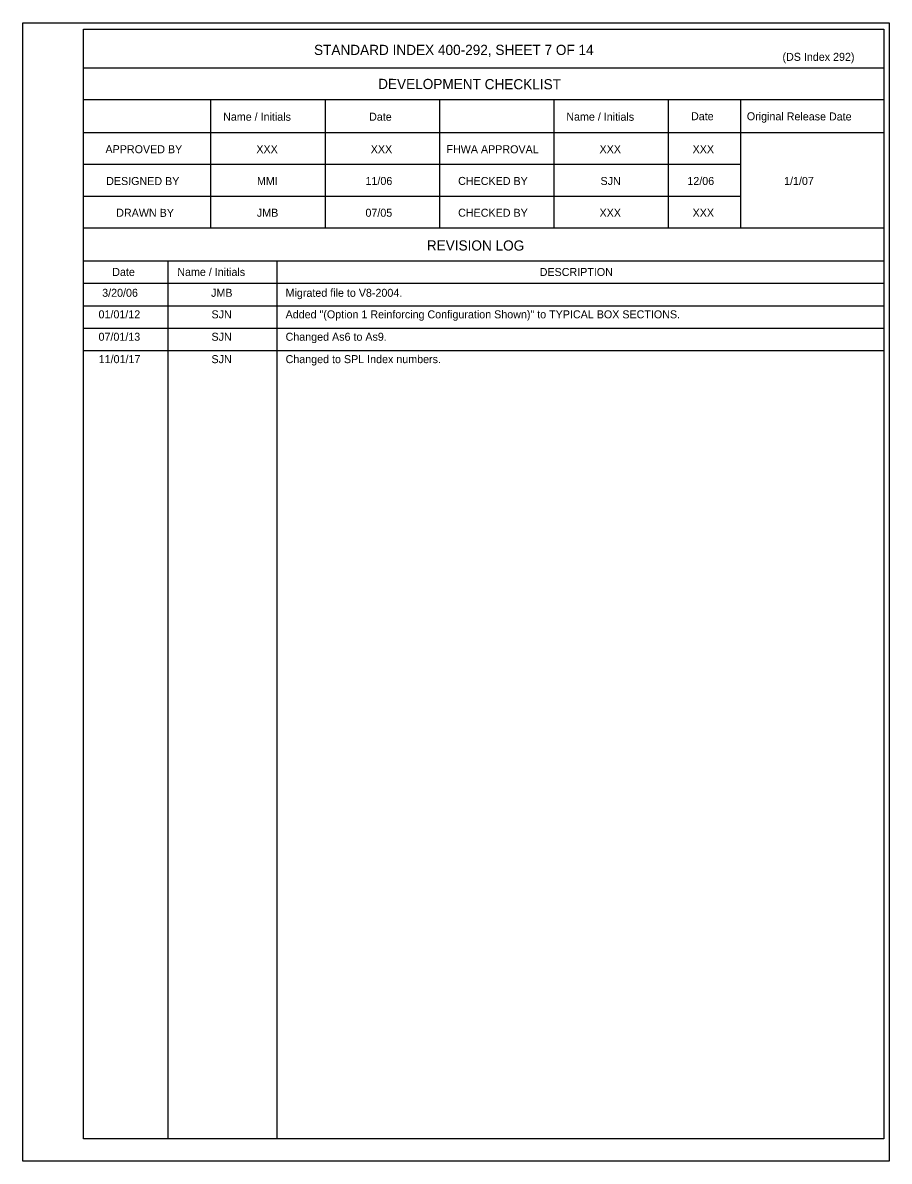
# Model space of a CAD drawing. Extents: x 10340.6 to 10393.7, y 76372.2 to 76398.3.
# Drawn here: x 10377.31 to 10393.67, y 76375.45 to 76396.95 of the extents above; entities that cross this region are included whole.
import ezdxf

# ---------------------------------------------------------------- set-up
doc = ezdxf.new("R2010")
doc.units = 0
for name, color, linetype in [('Border', 7, 'Continuous'), ('SheetBorder_dp', 7, 'Continuous'), ('TextMisc', 7, 'Continuous')]:
    doc.layers.add(name, color=color, linetype=linetype)

msp = doc.modelspace()

# ---------------------------------------------------------------- linework, layer by layer
at = {"layer": 'Border'}
for p, q in [((10393.566, 76396.094), (10378.455, 76396.094)), ((10393.566, 76395.494), (10378.455, 76395.494)), ((10380.855, 76395.494), (10380.855, 76393.073)), ((10383.015, 76395.494), (10383.015, 76393.073)), ((10385.175, 76395.494), (10385.175, 76393.073)), ((10387.335, 76395.494), (10387.335, 76393.073)), ((10389.495, 76395.494), (10389.495, 76393.073)), ((10390.857, 76395.494), (10390.857, 76393.073)), ((10393.566, 76394.873), (10378.455, 76394.873)), ((10390.857, 76394.273), (10378.455, 76394.273)), ((10390.857, 76393.673), (10378.455, 76393.673)), ((10393.566, 76393.073), (10378.455, 76393.073)), ((10393.566, 76392.452), (10378.455, 76392.452)), ((10380.046, 76392.452), (10380.046, 76375.872)), ((10382.102, 76392.452), (10382.102, 76375.872)), ((10393.566, 76392.029), (10378.455, 76392.029))]:
    msp.add_line(p, q, dxfattribs=at)
msp.add_lwpolyline([(10378.456, 76396.829), (10393.566, 76396.829), (10393.566, 76375.872), (10378.456, 76375.872)], close=True, dxfattribs=at)
at = {"layer": 'SheetBorder_dp'}
msp.add_line((10377.308, 76375.451), (10377.308, 76375.451), dxfattribs=at)
msp.add_lwpolyline([(10377.308, 76396.951), (10393.668, 76396.951), (10393.668, 76375.451), (10377.308, 76375.451)], close=True, dxfattribs=at)
at = {"layer": 'TextMisc'}
for p, q in [((10378.455, 76391.606), (10393.566, 76391.606)), ((10378.455, 76391.184), (10393.566, 76391.184)), ((10378.455, 76390.761), (10393.566, 76390.761))]:
    msp.add_line(p, q, dxfattribs=at)

# ---------------------------------------------------------------- texts
for s, height, p in [('STANDARD INDEX 400-292, SHEET 7 OF 14', 0.192, (10382.807, 76396.343)), ('(DS Index 292)', 0.1512, (10391.652, 76396.232)), ('XXX', 0.1512, (10381.718, 76394.488)), ('XXX', 0.1512, (10383.878, 76394.488)), ('XXX', 0.1512, (10388.198, 76394.488)), ('XXX', 0.1512, (10389.955, 76394.488)), ('MMI', 0.1512, (10381.73, 76393.888)), ('11/06', 0.1512, (10383.779, 76393.888)), ('SJN', 0.1512, (10388.216, 76393.888)), ('12/06', 0.1512, (10389.856, 76393.888)), ('1/1/07', 0.1512, (10391.682, 76393.888)), ('JMB', 0.1512, (10381.728, 76393.288)), ('07/05', 0.1512, (10383.778, 76393.288)), ('XXX', 0.1512, (10388.198, 76393.288)), ('XXX', 0.1512, (10389.955, 76393.288)), ('DESCRIPTION', 0.1512, (10387.068, 76392.169)), ('3/20/06', 0.1512, (10378.807, 76391.776)), ('Migrated file to V8-2004.', 0.1512, (10382.27, 76391.776)), ('JMB', 0.1512, (10380.863, 76391.776)), ('01/01/12', 0.1512, (10378.738, 76391.369)), ('SJN', 0.1512, (10380.871, 76391.369)), ('Added "(Option 1 Reinforcing Configuration Shown)" to TYPICAL BOX SECTIONS.', 0.1512, (10382.27, 76391.369)), ('07/01/13', 0.1512, (10378.738, 76390.946)), ('SJN', 0.1512, (10380.871, 76390.946)), ('Changed As6 to As9.', 0.1512, (10382.27, 76390.946)), ('11/01/17', 0.1512, (10378.741, 76390.523)), ('SJN', 0.1512, (10380.871, 76390.523)), ('Changed to SPL Index numbers.', 0.1512, (10382.27, 76390.523))]:
    msp.add_text(s, height=height, dxfattribs=at).set_placement(p)
for s, height, p in [('DEVELOPMENT CHECKLIST', 0.192, (10384.017, 76395.701)), ('Name / Initials', 0.1512, (10381.09, 76395.103)), ('Date', 0.1512, (10383.846, 76395.102)), ('Name / Initials', 0.1512, (10387.57, 76395.103)), ('Date', 0.1512, (10389.925, 76395.111)), ('Original Release Date', 0.1512, (10390.979, 76395.11)), ('APPROVED BY', 0.1512, (10378.869, 76394.489)), ('FHWA APPROVAL', 0.1512, (10385.307, 76394.489)), ('DESIGNED BY', 0.1512, (10378.882, 76393.888)), ('CHECKED BY', 0.1512, (10385.528, 76393.889)), ('DRAWN BY', 0.1512, (10379.072, 76393.288)), ('CHECKED BY', 0.1512, (10385.528, 76393.289)), ('REVISION LOG', 0.192, (10384.936, 76392.652)), ('Date', 0.1512, (10378.997, 76392.17)), ('Name / Initials', 0.1512, (10380.225, 76392.171))]:
    msp.add_text(s, height=height, rotation=359.8756, dxfattribs=at).set_placement(p)

doc.saveas('drawing.dxf')
